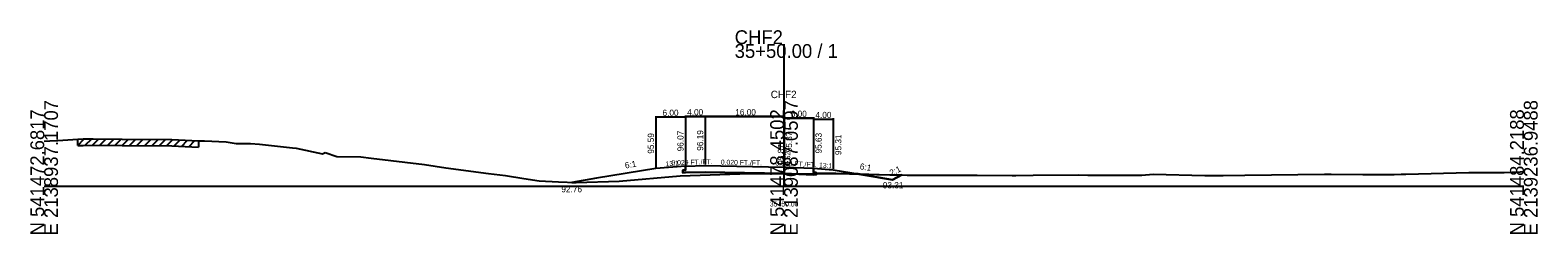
# Model space of a CAD drawing. Extents: x -12831 to 2303, y -10 to 39065.
# Drawn here: x 997.2 to 1302.8, y 10990.3 to 11031.7 of the extents above; entities that cross this region are included whole.
import ezdxf

# ---------------------------------------------------------------- set-up
doc = ezdxf.new("R2010")
doc.units = 0
for name, color, linetype in [('Level 5', 7, 'Continuous'), ('Level 53', 7, 'Continuous'), ('Level 54', 7, 'Continuous'), ('Level 55', 7, 'Continuous'), ('Level 7', 7, 'Continuous'), ('RD_GPK_XS_Cell', 7, 'Continuous'), ('RD_XS_EwShp', 7, 'Continuous'), ('RD_XS_ExGround', 7, 'Continuous'), ('RD_XS_ExPaveRet', 7, 'Continuous'), ('RD_XS_Pave', 7, 'Continuous'), ('RD_XS_TX_Baseline', 7, 'Continuous'), ('RD_XS_TX_Elev_EX', 7, 'Continuous'), ('RD_XS_TX_Elev_PR', 7, 'Continuous'), ('RD_XS_TX_Station', 7, 'Continuous')]:
    doc.layers.add(name, color=color, linetype=linetype)

msp = doc.modelspace()

# ---------------------------------------------------------------- linework, layer by layer
at = {"layer": 'Level 5'}
for p, q in [((1130, 11003.24), (1129.5, 11003.22)), ((1129.5, 11003.22), (1129.5, 11002.72)), ((1129.5, 11002.72), (1130, 11002.74)), ((1130, 11004.07), (1130, 11003.24)), ((1134, 11002.86), (1130, 11002.74)), ((1134, 11002.86), (1130, 11002.74)), ((1130, 11002.74), (1134, 11002.86)), ((1150, 11002.54), (1134, 11002.86)), ((1150, 11002.54), (1134, 11002.86)), ((1134, 11002.86), (1150, 11002.54)), ((1134, 11002.86), (1150, 11002.54)), ((1156, 11002.3), (1150, 11002.54)), ((1150, 11002.54), (1156, 11002.3)), ((1150, 11002.54), (1156, 11002.3)), ((1156, 11003.63), (1156, 11002.8)), ((1156, 11002.8), (1156.5, 11002.78)), ((1156.5, 11002.28), (1156, 11002.3)), ((1156.5, 11002.78), (1156.5, 11002.28))]:
    msp.add_line(p, q, dxfattribs=at)
at = {"layer": 'Level 54'}
for p, q in [((1124, 11014.22), (1124, 11003.79)), ((1130, 11014.02), (1124, 11014.02)), ((1130, 11014.34), (1130, 11004.27)), ((1130, 11014.34), (1130, 11004.27)), ((1130, 11014.34), (1130, 11004.27)), ((1130, 11014.22), (1130, 11004.27)), ((1130, 11014.14), (1134, 11014.14)), ((1130, 11014.14), (1134, 11014.14)), ((1134, 11014.14), (1130, 11014.14)), ((1134, 11014.34), (1134, 11004.39)), ((1134, 11014.34), (1134, 11004.39)), ((1134, 11014.34), (1134, 11004.39)), ((1134, 11014.34), (1134, 11004.39)), ((1134, 11014.34), (1134, 11004.39)), ((1134, 11014.34), (1134, 11004.39)), ((1134, 11014.34), (1134, 11004.39)), ((1134, 11014.14), (1150, 11014.14)), ((1134, 11014.14), (1150, 11014.14)), ((1150, 11014.14), (1134, 11014.14)), ((1150, 11014.14), (1134, 11014.14)), ((1150, 11014.34), (1150, 11004.07)), ((1150, 11014.34), (1150, 11004.07)), ((1150, 11014.34), (1150, 11004.07)), ((1150, 11014.34), (1150, 11004.07)), ((1150, 11014.02), (1150, 11004.07)), ((1150, 11014.02), (1150, 11004.07)), ((1150, 11014.02), (1150, 11004.07)), ((1150, 11013.82), (1156, 11013.82)), ((1156, 11013.82), (1150, 11013.82)), ((1156, 11013.82), (1150, 11013.82)), ((1156, 11014.02), (1156, 11003.83)), ((1156, 11014.02), (1156, 11003.83)), ((1156, 11014.02), (1156, 11003.83)), ((1156, 11013.78), (1156, 11003.83)), ((1160, 11013.78), (1160, 11003.51)), ((1156, 11013.58), (1160, 11013.58))]:
    msp.add_line(p, q, dxfattribs=at)
at = {"layer": 'Level 7'}
for p, q in [((1112, 11001.59), (1106.98, 11000.76)), ((1124, 11003.59), (1112, 11001.59)), ((1130, 11004.07), (1124, 11003.59)), ((1156, 11003.63), (1160, 11003.31)), ((1160, 11003.31), (1172, 11001.31)), ((1172, 11001.31), (1173.92, 11002.27))]:
    msp.add_line(p, q, dxfattribs=at)
at = {"layer": 'RD_GPK_XS_Cell'}
for p, q in [((1150, 11000), (1150, 11028.84)), ((1000, 11000), (1150, 11000)), ((1150, 11000), (1300, 11000))]:
    msp.add_line(p, q, dxfattribs=at)
at = {"layer": 'RD_XS_EwShp'}
for points in [[(1130, 11004.07), (1124, 11003.59), (1112, 11001.59), (1106.98, 11000.76), (1107.87, 11000.72), (1116.6, 11001.01), (1128.97, 11002.1), (1143.1, 11002.59), (1145.35, 11002.59), (1150, 11002.52), (1150.63, 11002.51), (1150, 11002.54), (1134, 11002.86), (1130, 11002.74), (1129.5, 11002.72), (1129.5, 11003.22), (1130, 11003.24)], [(1150.63, 11002.51), (1152.68, 11002.48), (1156.5, 11002.54), (1156.5, 11002.28), (1156, 11002.3)], [(1160, 11003.31), (1165.04, 11002.47), (1160.5, 11002.58), (1158.65, 11002.57), (1156.5, 11002.54), (1156.5, 11002.78), (1156, 11002.8), (1156, 11003.63)], [(1171.43, 11002.31), (1173.92, 11002.27), (1172, 11001.31), (1165.04, 11002.47)]]:
    msp.add_lwpolyline(points, close=True, dxfattribs=at)
at = {"layer": 'RD_XS_ExGround'}
for p, q in [((1000, 11009.11), (1001.14, 11009.19)), ((1001.14, 11009.19), (1002.78, 11009.29)), ((1002.78, 11009.29), (1006.81, 11009.57)), ((1006.81, 11009.57), (1007.88, 11009.58)), ((1007.88, 11009.58), (1009.94, 11009.61)), ((1009.94, 11009.61), (1015.79, 11009.55)), ((1015.79, 11009.55), (1025.88, 11009.46)), ((1025.88, 11009.46), (1031.31, 11009.21)), ((1031.31, 11009.21), (1031.62, 11009.19)), ((1031.62, 11009.19), (1032.52, 11009.17)), ((1032.52, 11009.17), (1036.91, 11009)), ((1036.91, 11009), (1038.91, 11008.68)), ((1038.91, 11008.68), (1041.82, 11008.65)), ((1041.82, 11008.65), (1043.67, 11008.54)), ((1043.67, 11008.54), (1050.33, 11007.79)), ((1050.33, 11007.79), (1051.08, 11007.69)), ((1051.08, 11007.69), (1056.46, 11006.55)), ((1056.46, 11006.55), (1056.98, 11006.81)), ((1056.98, 11006.81), (1059.32, 11006)), ((1059.32, 11006), (1064.19, 11005.93)), ((1064.19, 11005.93), (1066.33, 11005.66)), ((1066.33, 11005.66), (1077.14, 11004.38)), ((1077.14, 11004.38), (1081.43, 11003.74)), ((1081.43, 11003.74), (1090.08, 11002.55)), ((1090.08, 11002.55), (1093.55, 11002.17)), ((1093.55, 11002.17), (1097.27, 11001.57)), ((1097.27, 11001.57), (1100.33, 11001.1)), ((1116.6, 11001.01), (1128.97, 11002.1)), ((1128.97, 11002.1), (1143.1, 11002.59)), ((1143.1, 11002.59), (1145.35, 11002.59)), ((1145.35, 11002.59), (1150, 11002.52)), ((1150, 11002.52), (1152.68, 11002.48)), ((1152.68, 11002.48), (1158.65, 11002.57)), ((1158.65, 11002.57), (1160.5, 11002.58)), ((1160.5, 11002.58), (1171.43, 11002.31)), ((1171.43, 11002.31), (1174.99, 11002.25)), ((1174.99, 11002.25), (1179.78, 11002.25)), ((1179.78, 11002.25), (1182.3, 11002.26)), ((1182.3, 11002.26), (1184.22, 11002.26)), ((1184.22, 11002.26), (1189.19, 11002.25)), ((1189.19, 11002.25), (1196.25, 11002.17)), ((1196.25, 11002.17), (1197, 11002.16)), ((1197, 11002.16), (1200.52, 11002.2)), ((1200.52, 11002.2), (1209.78, 11002.31)), ((1209.78, 11002.31), (1211.6, 11002.21)), ((1211.6, 11002.21), (1222.56, 11002.24)), ((1222.56, 11002.24), (1224.85, 11002.41)), ((1224.85, 11002.41), (1235.35, 11002.13)), ((1235.35, 11002.13), (1239.04, 11002.15)), ((1239.04, 11002.15), (1243.44, 11002.24)), ((1243.44, 11002.24), (1259.59, 11002.42)), ((1259.59, 11002.42), (1260.91, 11002.43)), ((1260.91, 11002.43), (1267.36, 11002.38)), ((1267.36, 11002.38), (1273.7, 11002.39)), ((1273.7, 11002.39), (1275.16, 11002.42)), ((1275.16, 11002.42), (1276.08, 11002.43)), ((1276.08, 11002.43), (1288.82, 11002.77)), ((1288.82, 11002.77), (1291.76, 11002.8)), ((1291.76, 11002.8), (1296.02, 11002.78)), ((1296.02, 11002.78), (1299.26, 11002.9)), ((1299.26, 11002.9), (1300, 11002.96)), ((1100.33, 11001.1), (1104.3, 11000.85)), ((1104.3, 11000.85), (1107.87, 11000.72)), ((1107.87, 11000.72), (1116.6, 11001.01))]:
    msp.add_line(p, q, dxfattribs=at)
at = {"layer": 'RD_XS_ExPaveRet'}
for p, q in [((1006.81, 11008.27), (1008.13, 11009.59)), ((1006.81, 11008.27), (1006.81, 11009.57)), ((1006.81, 11008.27), (1007.88, 11008.28)), ((1007.88, 11008.28), (1009.94, 11008.31)), ((1008.31, 11008.29), (1009.63, 11009.61)), ((1009.81, 11008.31), (1011.1, 11009.6)), ((1009.94, 11008.31), (1015.79, 11008.25)), ((1011.31, 11008.3), (1012.6, 11009.58)), ((1012.81, 11008.28), (1014.1, 11009.57)), ((1014.31, 11008.27), (1015.6, 11009.55)), ((1015.79, 11008.25), (1025.88, 11008.16)), ((1015.81, 11008.25), (1017.1, 11009.54)), ((1017.31, 11008.24), (1018.6, 11009.53)), ((1018.81, 11008.22), (1020.1, 11009.51)), ((1020.31, 11008.21), (1021.6, 11009.5)), ((1021.81, 11008.2), (1023.1, 11009.49)), ((1023.31, 11008.18), (1024.6, 11009.47)), ((1024.81, 11008.17), (1026.09, 11009.45)), ((1025.88, 11008.16), (1031.31, 11007.91)), ((1026.31, 11008.14), (1027.55, 11009.38)), ((1027.81, 11008.07), (1029.05, 11009.32)), ((1029.31, 11008), (1030.55, 11009.25)), ((1031.31, 11009.21), (1031.31, 11007.91))]:
    msp.add_line(p, q, dxfattribs=at)
at = {"layer": 'RD_XS_Pave'}
for p, q in [((1130, 11004.07), (1134, 11004.19)), ((1134, 11004.19), (1150, 11003.87)), ((1150, 11003.87), (1156, 11003.63))]:
    msp.add_line(p, q, dxfattribs=at)

# ---------------------------------------------------------------- texts
at = {"layer": 'Level 53'}
for s, rotation, p in [('95.59', 90, (1123.63, 11006.59)), ('96.07', 90, (1129.63, 11007.07)), ('96.19', 90, (1133.62, 11007.19)), ('96.19', 90, (1133.62, 11007.19)), ('95.87', 90, (1151.63, 11006.87)), ('95.87', 90, (1151.63, 11006.87)), ('95.63', 90, (1157.63, 11006.63)), ('95.31', 90, (1161.63, 11006.31)), ('6:1', 9.4623, (1117.84, 11003.58)), ('6:1', 350.5377, (1165.3, 11003.44))]:
    msp.add_text(s, height=1.25, rotation=rotation, dxfattribs=at).set_placement(p)
for s, p in [('92.76', (1104.86, 10998.76)), ('93.31', (1170.03, 10999.56))]:
    msp.add_text(s, height=1.25, dxfattribs=at).set_placement(p)
at = {"layer": 'Level 54'}
for s, p in [('6.00', (1125.37, 11014.27)), ('4.00', (1130.37, 11014.39)), ('4.00', (1130.37, 11014.39)), ('4.00', (1130.37, 11014.39)), ('16.00', (1140.12, 11014.39)), ('16.00', (1140.12, 11014.39)), ('16.00', (1140.12, 11014.39)), ('16.00', (1140.12, 11014.39)), ('6.00', (1151.37, 11014.07)), ('6.00', (1151.37, 11014.07)), ('6.00', (1151.37, 11014.07)), ('4.00', (1156.37, 11013.83))]:
    msp.add_text(s, height=1.25, dxfattribs=at).set_placement(p)
at = {"layer": 'Level 55'}
for s, height, rotation, p in [('13:1', 1, 4.5739, (1126.03, 11004.01)), ('0.029 FT./FT.', 1, 1.6801, (1127.2, 11004.24)), ('0.029 FT./FT.', 1, 1.6801, (1127.2, 11004.24)), ('0.029 FT./FT.', 1, 1.6801, (1127.2, 11004.24)), ('0.020 FT./FT.', 1, 358.8542, (1137.18, 11004.38)), ('0.020 FT./FT.', 1, 358.8542, (1137.18, 11004.38)), ('0.020 FT./FT.', 1, 358.8542, (1137.18, 11004.38)), ('0.020 FT./FT.', 1, 358.8542, (1137.18, 11004.38)), ('0.040 FT./FT.', 1, 357.7094, (1148.24, 11004.19)), ('0.040 FT./FT.', 1, 357.7094, (1148.24, 11004.19)), ('0.040 FT./FT.', 1, 357.7094, (1148.24, 11004.19)), ('13:1', 1, 355.4261, (1157.07, 11003.8)), ('2:1', 1.25, 26.5651, (1171.78, 11002.04))]:
    msp.add_text(s, height=height, rotation=rotation, dxfattribs=at).set_placement(p)
at = {"layer": 'RD_GPK_XS_Cell'}
for s, p in [('CHF2', (1140, 11028.84)), ('35+50.00 / 1', (1140, 11026.04))]:
    msp.add_text(s, height=2.8, dxfattribs=at).set_placement(p)
for s, p in [('E 2138937.1707', (1002.8, 10990)), ('E 2139087.0597', (1152.8, 10990)), ('E 2139236.9488', (1302.8, 10990)), ('N 541472.6817', (1000, 10990)), ('N 541478.4502', (1150, 10990)), ('N 541484.2188', (1300, 10990))]:
    msp.add_text(s, height=2.8, rotation=90, dxfattribs=at).set_placement(p)
at = {"layer": 'RD_XS_TX_Baseline'}
msp.add_text('CHF2', height=1.5, dxfattribs=at).set_placement((1147.31, 11017.87))
at = {"layer": 'RD_XS_TX_Elev_EX'}
msp.add_text('94.52', height=1, rotation=90, dxfattribs=at).set_placement((1151.25, 11003.52))
at = {"layer": 'RD_XS_TX_Elev_PR'}
msp.add_text(' 95.87', height=1.25, rotation=90, dxfattribs=at).set_placement((1150, 11003.87))
at = {"layer": 'RD_XS_TX_Station'}
msp.add_text('35+50.00', height=1, dxfattribs=at).set_placement((1147.12, 10995.87))

doc.saveas('drawing.dxf')
